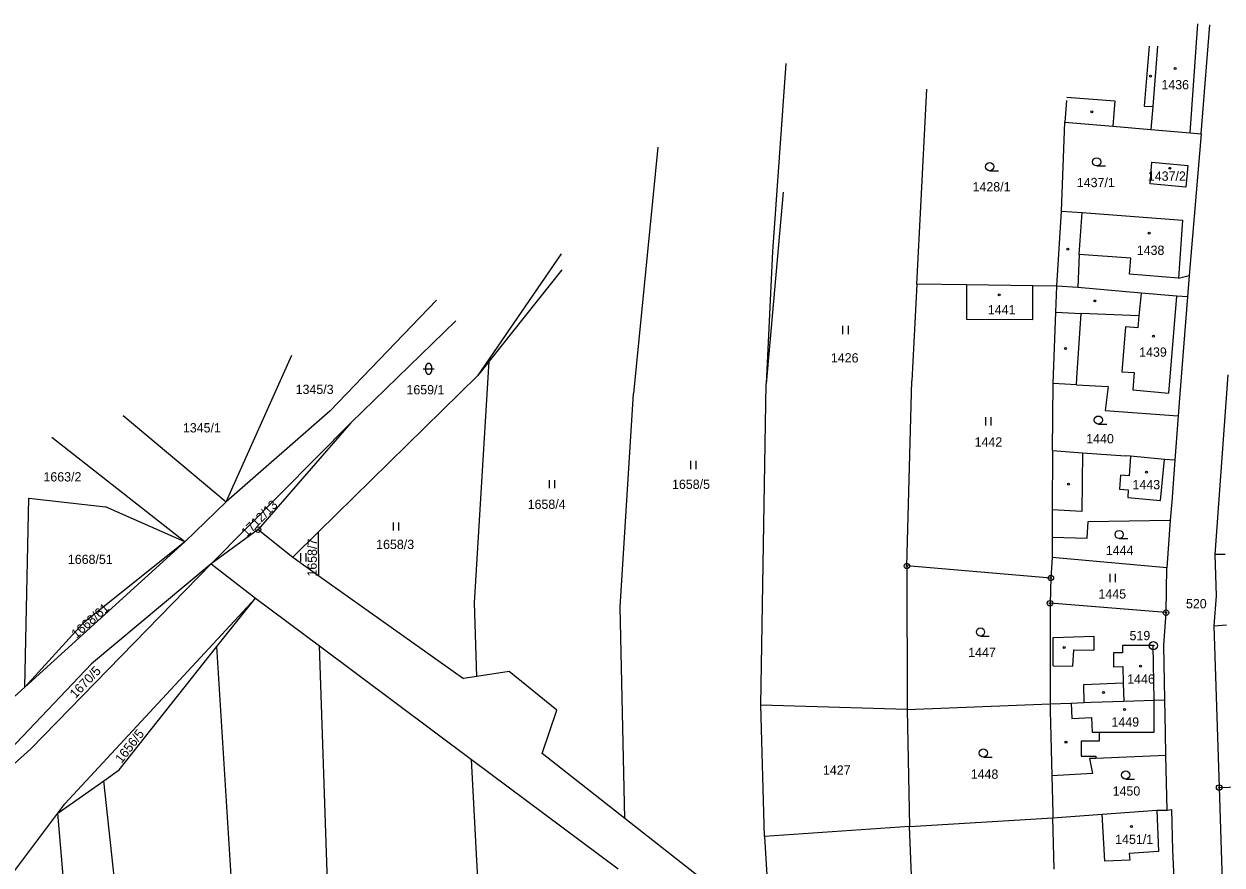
# Model space of a CAD drawing. Extents: x -763296 to -761805, y -1153670 to -1152034.
# Drawn here: x -762975 to -762755.5, y -1152434.4 to -1152280.4 of the extents above; entities that cross this region are included whole.
import ezdxf

# ---------------------------------------------------------------- set-up
doc = ezdxf.new("R2010")
doc.units = 0
for name, color, linetype in [('Vrstva 1', 7, 'Continuous'), ('Vrstva 17', 7, 'Continuous'), ('Vrstva 18', 7, 'Continuous'), ('Vrstva 19', 7, 'Continuous'), ('Vrstva 24', 7, 'Continuous'), ('Vrstva 25', 7, 'Continuous'), ('Vrstva 4', 7, 'Continuous'), ('Vrstva 6', 7, 'Continuous')]:
    doc.layers.add(name, color=color, linetype=linetype)

msp = doc.modelspace()

# ---------------------------------------------------------------- linework, layer by layer
at = {"layer": 'Vrstva 1'}
for p, q in [((-762759.29, -1152300.56), (-762757.74, -1152280.61)), ((-762810.62, -1152312.73), (-762809.57, -1152292.36)), ((-762784, -1152294.48), (-762784.27, -1152298.43)), ((-762784.9, -1152314.69), (-762784.27, -1152298.43)), ((-762784.27, -1152298.43), (-762775.49, -1152299.18)), ((-762775.49, -1152299.18), (-762768.51, -1152299.77)), ((-762768.51, -1152299.77), (-762761.34, -1152300.36)), ((-762759.29, -1152300.56), (-762761.52, -1152326.52)), ((-762761.34, -1152300.36), (-762759.29, -1152300.56)), ((-762768.67, -1152309.73), (-762768.36, -1152305.72)), ((-762768.36, -1152305.72), (-762761.78, -1152306.35)), ((-762761.78, -1152306.35), (-762762.15, -1152310.29)), ((-762835.92, -1152311.26), (-762839.01, -1152346.35)), ((-762762.15, -1152310.29), (-762768.67, -1152309.73)), ((-762811.42, -1152328.08), (-762810.62, -1152312.73)), ((-762785.75, -1152328.42), (-762784.9, -1152314.69)), ((-762784.9, -1152314.69), (-762781.11, -1152314.97)), ((-762781.11, -1152314.97), (-762762.72, -1152316.35)), ((-762762.72, -1152316.35), (-762763.49, -1152327.01)), ((-762876.54, -1152322.52), (-762891.88, -1152344.87)), ((-762763.49, -1152327.01), (-762761.52, -1152326.52)), ((-762761.52, -1152326.52), (-762761.85, -1152330.42)), ((-762811.42, -1152328.08), (-762812.34, -1152345.76)), ((-762802.29, -1152328.2), (-762811.42, -1152328.08)), ((-762802.29, -1152328.2), (-762802.33, -1152334.46)), ((-762790.13, -1152328.36), (-762802.29, -1152328.2)), ((-762785.75, -1152328.42), (-762790.13, -1152328.36)), ((-762790.13, -1152334.56), (-762790.13, -1152328.36)), ((-762785.94, -1152333.22), (-762785.75, -1152328.42)), ((-762781.93, -1152328.7), (-762785.75, -1152328.42)), ((-762770.3, -1152329.71), (-762781.93, -1152328.7)), ((-762899.42, -1152331.01), (-762918.95, -1152351.35)), ((-762763.77, -1152330.25), (-762770.3, -1152329.71)), ((-762761.85, -1152330.42), (-762763.77, -1152330.25)), ((-762761.85, -1152330.42), (-762763.23, -1152348.16)), ((-762786.46, -1152346.28), (-762785.94, -1152333.22)), ((-762895.87, -1152334.79), (-762915.11, -1152353.48)), ((-762802.33, -1152334.46), (-762790.13, -1152334.56)), ((-762891.88, -1152344.87), (-762921.02, -1152373.41)), ((-762839.97, -1152405.14), (-762839.01, -1152346.35)), ((-762813.23, -1152379.68), (-762812.34, -1152345.76)), ((-762786.58, -1152358.55), (-762786.46, -1152346.28)), ((-762782.16, -1152346.49), (-762786.46, -1152346.28)), ((-762782.16, -1152346.49), (-762776.38, -1152346.83)), ((-762754.43, -1152344.69), (-762756.81, -1152377.58)), ((-762776.38, -1152346.83), (-762776.91, -1152351.21)), ((-762763.23, -1152348.16), (-762763.54, -1152352.21)), ((-762956.82, -1152352.14), (-762937.95, -1152367.93)), ((-762918.95, -1152351.35), (-762937.95, -1152367.93)), ((-762776.91, -1152351.21), (-762763.54, -1152352.21)), ((-762763.54, -1152352.21), (-762764.17, -1152360.33)), ((-762915.11, -1152353.48), (-762932.1, -1152373.03)), ((-762945.48, -1152375.28), (-762969.85, -1152356.14)), ((-762786.58, -1152358.55), (-762786.62, -1152369.43)), ((-762786.58, -1152358.55), (-762781.04, -1152358.94)), ((-762781.04, -1152358.94), (-762773.18, -1152359.49)), ((-762772.24, -1152359.58), (-762773.18, -1152359.49)), ((-762766.04, -1152360.16), (-762772.24, -1152359.58)), ((-762764.17, -1152360.33), (-762766.04, -1152360.16)), ((-762764.17, -1152360.33), (-762764.72, -1152367.91)), ((-762974.06, -1152367.27), (-762960.01, -1152368.87)), ((-762937.95, -1152367.93), (-762945.48, -1152375.28)), ((-762764.72, -1152367.91), (-762764.97, -1152371.28)), ((-762945.48, -1152375.28), (-762960.01, -1152368.87)), ((-762786.62, -1152369.43), (-762786.64, -1152374.43)), ((-762932.1, -1152373.03), (-762940.65, -1152379.29)), ((-762932.1, -1152373.03), (-762925.75, -1152378.05)), ((-762780.21, -1152374.56), (-762780.03, -1152371.51)), ((-762780.03, -1152371.51), (-762764.97, -1152371.28)), ((-762764.97, -1152371.28), (-762765.61, -1152380.02)), ((-762945.48, -1152375.28), (-762974.84, -1152401.85)), ((-762921.02, -1152373.41), (-762925.75, -1152378.05)), ((-762786.64, -1152374.43), (-762786.61, -1152378.14)), ((-762786.64, -1152374.43), (-762780.21, -1152374.56)), ((-762940.65, -1152379.29), (-762962.59, -1152397.59)), ((-762940.65, -1152379.29), (-762932.58, -1152385.57)), ((-762925.75, -1152378.05), (-762920.96, -1152381.46)), ((-762813.23, -1152379.68), (-762813.17, -1152405.97)), ((-762786.85, -1152381.89), (-762813.23, -1152379.68)), ((-762786.61, -1152378.14), (-762786.85, -1152381.89)), ((-762765.61, -1152380.02), (-762786.61, -1152378.14)), ((-762754.92, -1152377.55), (-762756.81, -1152377.58)), ((-762756.81, -1152377.58), (-762756.57, -1152385.15)), ((-762920.96, -1152381.46), (-762894.48, -1152400.29)), ((-762786.85, -1152381.89), (-762787.01, -1152386.5)), ((-762765.75, -1152388.22), (-762765.61, -1152380.02)), ((-762932.58, -1152385.57), (-762967.49, -1152423.25)), ((-762932.58, -1152385.57), (-762920.86, -1152394.31)), ((-762756.57, -1152385.15), (-762757, -1152390.62)), ((-762768.11, -1152388.03), (-762787.01, -1152386.5)), ((-762787.01, -1152386.5), (-762787.01, -1152404.91)), ((-762765.75, -1152388.22), (-762768.11, -1152388.03)), ((-762766.15, -1152394.22), (-762765.75, -1152388.22)), ((-762757, -1152390.62), (-762754.69, -1152390.45)), ((-762757, -1152390.62), (-762756.02, -1152420.25)), ((-762920.86, -1152394.31), (-762892.96, -1152415.12)), ((-762765.99, -1152404.17), (-762766.15, -1152394.22)), ((-762989.06, -1152425.44), (-762962.59, -1152397.59)), ((-762886.1, -1152399.02), (-762892.03, -1152399.92)), ((-762877.36, -1152406.11), (-762886.1, -1152399.02)), ((-762892.03, -1152399.92), (-762894.48, -1152400.29)), ((-762974.84, -1152401.85), (-762997.4, -1152422.3)), ((-762839.29, -1152429.22), (-762839.97, -1152405.14)), ((-762813.17, -1152405.97), (-762839.97, -1152405.14)), ((-762813.17, -1152405.97), (-762787.01, -1152404.91)), ((-762813.17, -1152405.97), (-762812.76, -1152427.39)), ((-762787.01, -1152404.91), (-762783.14, -1152404.77)), ((-762787.01, -1152404.91), (-762786.98, -1152406.23)), ((-762783.14, -1152404.77), (-762780.81, -1152404.69)), ((-762780.81, -1152404.69), (-762779.5, -1152404.64)), ((-762779.5, -1152404.64), (-762773.51, -1152404.43)), ((-762773.51, -1152404.43), (-762767.92, -1152404.26)), ((-762767.92, -1152404.26), (-762765.99, -1152404.17)), ((-762765.86, -1152410.09), (-762765.99, -1152404.17)), ((-762880.04, -1152414.01), (-762877.36, -1152406.11)), ((-762786.98, -1152406.23), (-762786.86, -1152410.84)), ((-762765.77, -1152414.41), (-762765.86, -1152410.09)), ((-762786.86, -1152410.84), (-762786.67, -1152418.11)), ((-762864.9, -1152425.9), (-762880.04, -1152414.01)), ((-762765.77, -1152414.41), (-762778.6, -1152414.91)), ((-762765.55, -1152424.36), (-762765.77, -1152414.41)), ((-762892.96, -1152415.12), (-762866.1, -1152435.15)), ((-762778.6, -1152414.91), (-762779.78, -1152414.96)), ((-762779.78, -1152414.96), (-762779.2, -1152417.67)), ((-762779.2, -1152417.67), (-762786.67, -1152418.11)), ((-762786.67, -1152418.11), (-762786.49, -1152425)), ((-762756.02, -1152420.25), (-762726.41, -1152419.22)), ((-762756.02, -1152420.25), (-762755.36, -1152440.1)), ((-762968.78, -1152424.96), (-762967.49, -1152423.25)), ((-762978.68, -1152438.1), (-762968.78, -1152424.96)), ((-762812.76, -1152427.39), (-762786.47, -1152425.81)), ((-762786.49, -1152425), (-762786.47, -1152425.81)), ((-762786.47, -1152425.81), (-762777.48, -1152425.15)), ((-762786.26, -1152435.18), (-762786.47, -1152425.81)), ((-762777.48, -1152425.15), (-762767.43, -1152424.4)), ((-762767.43, -1152424.4), (-762765.55, -1152424.36)), ((-762765.55, -1152424.36), (-762764.78, -1152424.25)), ((-762764.78, -1152424.25), (-762764.6, -1152431.69)), ((-762838.3, -1152446.79), (-762864.9, -1152425.9)), ((-762812.76, -1152427.39), (-762839.29, -1152429.22)), ((-762811.78, -1152449.73), (-762812.76, -1152427.39)), ((-762764.6, -1152431.69), (-762764.32, -1152436.89))]:
    msp.add_line(p, q, dxfattribs=at)
at = {"layer": 'Vrstva 24'}
for centre, radius in [((-762932.1, -1152373.03), 0.5), ((-762932.1, -1152373.03), 0.1), ((-762813.23, -1152379.68), 0.5), ((-762813.23, -1152379.68), 0.1), ((-762786.85, -1152381.89), 0.5), ((-762786.85, -1152381.89), 0.1), ((-762787.01, -1152386.5), 0.5), ((-762787.01, -1152386.5), 0.1), ((-762765.75, -1152388.22), 0.5), ((-762765.75, -1152388.22), 0.1), ((-762768.07, -1152394.26), 0.75), ((-762768.07, -1152394.26), 0.1), ((-762756.02, -1152420.25), 0.5), ((-762756.02, -1152420.25), 0.1)]:
    msp.add_circle(centre, radius, dxfattribs=at)
at = {"layer": 'Vrstva 25'}
for p, q in [((-762778.45, -1152306.44), (-762776.85, -1152306.44)), ((-762798.07, -1152307.31), (-762796.47, -1152307.31)), ((-762824.95, -1152337.24), (-762824.95, -1152335.74)), ((-762823.95, -1152337.24), (-762823.95, -1152335.74)), ((-762901.83, -1152343.58), (-762899.83, -1152343.58)), ((-762901.33, -1152344.08), (-762901.33, -1152343.08)), ((-762900.33, -1152343.08), (-762900.33, -1152344.08)), ((-762798.79, -1152353.95), (-762798.79, -1152352.45)), ((-762797.79, -1152353.95), (-762797.79, -1152352.45)), ((-762778.17, -1152353.72), (-762776.57, -1152353.72)), ((-762852.82, -1152361.94), (-762852.82, -1152360.44)), ((-762851.82, -1152361.94), (-762851.82, -1152360.44)), ((-762878.72, -1152365.45), (-762878.72, -1152363.95)), ((-762877.72, -1152365.45), (-762877.72, -1152363.95)), ((-762907.28, -1152373.2), (-762907.28, -1152371.7)), ((-762906.28, -1152373.2), (-762906.28, -1152371.7)), ((-762774.33, -1152374.66), (-762772.73, -1152374.66)), ((-762924.28, -1152378.83), (-762924.28, -1152377.33)), ((-762923.28, -1152378.83), (-762923.28, -1152377.33)), ((-762776.02, -1152382.62), (-762776.02, -1152381.12)), ((-762775.02, -1152382.62), (-762775.02, -1152381.12)), ((-762799.74, -1152392.52), (-762798.14, -1152392.52)), ((-762799.22, -1152414.68), (-762797.62, -1152414.68)), ((-762773.15, -1152418.71), (-762771.55, -1152418.71))]:
    msp.add_line(p, q, dxfattribs=at)
for centre, radius in [((-762764.08, -1152288.58), 0.175), ((-762768.61, -1152289.99), 0.175), ((-762779.37, -1152296.52), 0.175), ((-762778.45, -1152305.69), 0.75), ((-762798.07, -1152306.56), 0.75), ((-762765.04, -1152306.87), 0.175), ((-762768.83, -1152318.76), 0.175), ((-762783.74, -1152321.65), 0.175), ((-762796.3, -1152330.04), 0.175), ((-762778.81, -1152331.16), 0.175), ((-762768.04, -1152337.61), 0.175), ((-762784.18, -1152339.88), 0.175), ((-762778.17, -1152352.97), 0.75), ((-762769.34, -1152362.52), 0.175), ((-762783.64, -1152364.7), 0.175), ((-762774.33, -1152373.91), 0.75), ((-762799.74, -1152391.77), 0.75), ((-762784.41, -1152394.62), 0.175), ((-762770.43, -1152398.02), 0.175), ((-762777.19, -1152402.84), 0.175), ((-762773.35, -1152405.96), 0.175), ((-762784.08, -1152411.95), 0.175), ((-762799.22, -1152413.93), 0.75), ((-762773.15, -1152417.96), 0.75), ((-762772.07, -1152427.36), 0.175)]:
    msp.add_circle(centre, radius, dxfattribs=at)
for centre, start, end in [((-762900.83, -1152343.08), 0, 180), ((-762900.83, -1152344.08), 180, 0)]:
    msp.add_arc(centre, 0.5, start, end, dxfattribs=at)
at = {"layer": 'Vrstva 4'}
for p, q in [((-762761.34, -1152300.36), (-762759.9, -1152280.44)), ((-762768.82, -1152284.49), (-762769.76, -1152295.46)), ((-762767.32, -1152284.52), (-762768.17, -1152295.58)), ((-762783.95, -1152293.83), (-762775.16, -1152294.5)), ((-762775.16, -1152294.5), (-762775.49, -1152299.18)), ((-762769.76, -1152295.46), (-762768.17, -1152295.58)), ((-762768.17, -1152295.58), (-762768.51, -1152299.77)), ((-762781.67, -1152322.64), (-762781.11, -1152314.97)), ((-762781.67, -1152322.64), (-762781.93, -1152328.7)), ((-762772.18, -1152323.35), (-762781.67, -1152322.64)), ((-762772.42, -1152326.28), (-762772.18, -1152323.35)), ((-762763.49, -1152327.01), (-762772.42, -1152326.28)), ((-762770.3, -1152329.71), (-762770.75, -1152333.9)), ((-762765.23, -1152348.04), (-762763.77, -1152330.25)), ((-762785.94, -1152333.22), (-762781.32, -1152333.43)), ((-762782.1, -1152345.25), (-762781.32, -1152333.43)), ((-762770.75, -1152333.9), (-762781.32, -1152333.43)), ((-762770.75, -1152333.9), (-762770.93, -1152336.07)), ((-762773.21, -1152335.89), (-762773.87, -1152344.12)), ((-762770.93, -1152336.07), (-762773.21, -1152335.89)), ((-762773.87, -1152344.12), (-762771.6, -1152344.27)), ((-762771.6, -1152344.27), (-762771.82, -1152347.44)), ((-762782.16, -1152346.49), (-762782.1, -1152345.25)), ((-762771.82, -1152347.44), (-762765.23, -1152348.04)), ((-762781.04, -1152358.94), (-762781.21, -1152369.71)), ((-762772.24, -1152359.58), (-762772.5, -1152363.17)), ((-762766.79, -1152367.72), (-762766.04, -1152360.16)), ((-762774.09, -1152363.03), (-762774.31, -1152365.59)), ((-762772.5, -1152363.17), (-762774.09, -1152363.03)), ((-762774.31, -1152365.59), (-762772.69, -1152365.75)), ((-762772.69, -1152365.75), (-762772.77, -1152367.15)), ((-762772.77, -1152367.15), (-762766.79, -1152367.72)), ((-762781.21, -1152369.71), (-762786.62, -1152369.43)), ((-762786.43, -1152392.78), (-762778.96, -1152392.54)), ((-762786.43, -1152397.98), (-762786.43, -1152392.78)), ((-762778.96, -1152392.54), (-762778.97, -1152395.07)), ((-762782.81, -1152398.02), (-762782.67, -1152395.05)), ((-762782.67, -1152395.05), (-762778.97, -1152395.07)), ((-762768.09, -1152394.24), (-762773.72, -1152394.26)), ((-762773.72, -1152394.26), (-762773.7, -1152395.56)), ((-762767.92, -1152404.26), (-762768.09, -1152394.24)), ((-762773.7, -1152395.56), (-762775.38, -1152395.6)), ((-762775.38, -1152395.6), (-762775.38, -1152398.13)), ((-762786.43, -1152397.98), (-762782.81, -1152398.02)), ((-762775.38, -1152398.13), (-762773.66, -1152398.1)), ((-762773.66, -1152398.1), (-762773.59, -1152401.16)), ((-762773.59, -1152401.16), (-762780.89, -1152401.42)), ((-762780.89, -1152401.42), (-762780.81, -1152404.69)), ((-762773.59, -1152401.16), (-762773.51, -1152404.43)), ((-762783.14, -1152404.77), (-762782.99, -1152407.59)), ((-762767.94, -1152410.12), (-762767.92, -1152404.26)), ((-762782.99, -1152407.59), (-762779.4, -1152407.42)), ((-762779.4, -1152407.42), (-762779.3, -1152410.09)), ((-762779.3, -1152410.09), (-762777.98, -1152410.09)), ((-762777.98, -1152410.09), (-762777.98, -1152411.75)), ((-762777.98, -1152410.09), (-762767.94, -1152410.12)), ((-762777.98, -1152411.75), (-762781.33, -1152411.75)), ((-762781.33, -1152411.75), (-762781.33, -1152414.53)), ((-762781.33, -1152414.53), (-762778.6, -1152414.53)), ((-762778.6, -1152414.53), (-762778.6, -1152414.91)), ((-762776.95, -1152433.73), (-762777.48, -1152425.15)), ((-762767.43, -1152424.4), (-762767.14, -1152431.97)), ((-762767.14, -1152431.97), (-762772.48, -1152432.35)), ((-762772.48, -1152432.35), (-762772.38, -1152433.57)), ((-762772.38, -1152433.57), (-762776.95, -1152433.73))]:
    msp.add_line(p, q, dxfattribs=at)
at = {"layer": 'Vrstva 6'}
for p, q in [((-762835.39, -1152287.66), (-762837.83, -1152322.1)), ((-762858.83, -1152302.98), (-762863.32, -1152348.12)), ((-762837.83, -1152322.1), (-762839.01, -1152346.35)), ((-762876.47, -1152325.44), (-762889.76, -1152342.2)), ((-762937.95, -1152367.93), (-762925.89, -1152341.06)), ((-762892.44, -1152386.42), (-762889.76, -1152342.2)), ((-762889.76, -1152342.2), (-762891.88, -1152344.87)), ((-762865.78, -1152387.23), (-762863.32, -1152348.12)), ((-762940.65, -1152379.29), (-762915.11, -1152353.48)), ((-762974.84, -1152401.85), (-762974.06, -1152367.27)), ((-762945.48, -1152375.28), (-762964.21, -1152390.19)), ((-762920.96, -1152381.46), (-762921.02, -1152373.41)), ((-762973.69, -1152413.15), (-762940.65, -1152379.29)), ((-762939.63, -1152394.44), (-762932.58, -1152385.57)), ((-762892.03, -1152399.92), (-762892.44, -1152386.42)), ((-762864.9, -1152425.9), (-762865.78, -1152387.23)), ((-762964.21, -1152390.19), (-762974.84, -1152401.85)), ((-762957.53, -1152417.01), (-762939.63, -1152394.44)), ((-762935.18, -1152465.77), (-762939.63, -1152394.44)), ((-762917.97, -1152478.12), (-762920.86, -1152394.31)), ((-762993.56, -1152430.81), (-762973.69, -1152413.15)), ((-762960.36, -1152419.02), (-762957.53, -1152417.01)), ((-762887.48, -1152522.25), (-762892.96, -1152415.12)), ((-762968.78, -1152424.96), (-762960.36, -1152419.02)), ((-762943.84, -1152570.41), (-762960.36, -1152419.02)), ((-762967.58, -1152438.52), (-762968.78, -1152424.96)), ((-762839.29, -1152429.22), (-762838.3, -1152446.79))]:
    msp.add_line(p, q, dxfattribs=at)

# ---------------------------------------------------------------- texts
at = {"layer": 'Vrstva 17'}
for s, p in [('520', (-762762.101, -1152387.43)), ('519', (-762772.433, -1152393.27))]:
    msp.add_text(s, height=1.7, dxfattribs=at).set_placement(p)
at = {"layer": 'Vrstva 18'}
for s, p in [('1428/1', (-762801.197, -1152311.1)), ('1437/1', (-762782.093, -1152310.32)), ('1426', (-762827.149, -1152342.42)), ('1345/3', (-762925.207, -1152348.19)), ('1659/1', (-762904.903, -1152348.26)), ('1345/1', (-762945.86, -1152355.23)), ('1440', (-762780.372, -1152357.23)), ('1442', (-762800.819, -1152357.82)), ('1663/2', (-762971.405, -1152364.21)), ('1658/5', (-762856.255, -1152365.57)), ('1658/4', (-762882.698, -1152369.23)), ('1658/3', (-762910.455, -1152376.58)), ('1668/51', (-762966.929, -1152379.31)), ('1444', (-762776.775, -1152377.66)), ('1445', (-762778.122, -1152385.65)), ('1447', (-762801.995, -1152396.35)), ('1427', (-762828.609, -1152417.91)), ('1448', (-762801.536, -1152418.64)), ('1450', (-762775.539, -1152421.73))]:
    msp.add_text(s, height=1.7, dxfattribs=at).set_placement(p)
for s, rotation, p in [('1712/13', 45.26367, (-762934.137, -1152374.472)), ('1658/7', 89.6106, (-762921.346, -1152381.628)), ('1668/61', 41.59674, (-762965.368, -1152393.06)), ('1670/5', 46.29499, (-762965.541, -1152404.043)), ('1656/5', 52.25375, (-762957.088, -1152415.929))]:
    msp.add_text(s, height=1.7, rotation=rotation, dxfattribs=at).set_placement(p)
at = {"layer": 'Vrstva 19'}
for s, p in [('1436', (-762766.602, -1152292.41)), ('1437/2', (-762769.085, -1152309.15)), ('1438', (-762771.113, -1152322.72)), ('1441', (-762798.397, -1152333.61)), ('1439', (-762770.672, -1152341.37)), ('1443', (-762771.892, -1152365.63)), ('1446', (-762772.865, -1152401.22)), ('1449', (-762775.745, -1152409.1)), ('1451/1', (-762775.065, -1152430.57))]:
    msp.add_text(s, height=1.7, dxfattribs=at).set_placement(p)

doc.saveas('drawing.dxf')
